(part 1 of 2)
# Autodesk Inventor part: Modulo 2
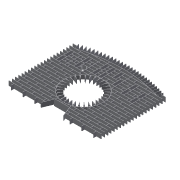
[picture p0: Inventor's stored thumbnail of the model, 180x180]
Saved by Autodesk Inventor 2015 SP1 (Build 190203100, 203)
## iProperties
Created: 2015-04
Part Number: Modulo 2
Material: Generic
Document SubType Name: Modeling
Designer: treina2
Density: 1 g/cm^3
Appearance: Default
Author: treina2
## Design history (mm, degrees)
sketch "Sketch1"
  geometry: L1 (740, 1360)-(740, 1418) reference; L2 (954, 1088)-(954, 1146) reference; L3 (740, 1088)-(740, 1146) reference; L4 (740, 1292)-(740, 1350) reference; L5 (954, 1224)-(954, 1282) reference; L6 (954, 1360)-(954, 1418) reference; L7 (954, 1292)-(954, 1350) reference; L8 (954, 1156)-(954, 1214) reference; L9 (740, 1156)-(740, 1214) reference; L10 (740, 1224)-(740, 1282) reference; L11 (1990, 534)-(1990, 544) reference; L12 (1990, 1350)-(1990, 1360) reference; L13 (740, 262)-(500, 262) reference; L14 (500, 262)-(500, 204) reference; L15 (1875, 136)-(1990, 136) reference; L16 (1990, 136)-(1990, 194) reference; L17 (1990, 194)-(1875, 194) reference; L18 (1875, 194)-(1875, 136) reference; L19 (250, 68)-(490, 68) reference; L20 (490, 68)-(490, 126) reference; L21 (490, 126)-(250, 126) reference; L22 (250, 126)-(250, 68) reference; L23 (750, 68)-(777.045, 68) reference; L24 (1250, 204)-(1490, 204) reference; L25 (1490, 204)-(1490, 262) reference; L26 (1490, 262)-(1250, 262) reference; L27 (1250, 262)-(1250, 204) reference; L28 (1500, 204)-(1740, 204) reference; L29 (1740, 204)-(1740, 262) reference; L30 (1740, 262)-(1500, 262) reference; L31 (1500, 262)-(1500, 204) reference; L32 (125, 136)-(365, 136) reference; L33 (365, 136)-(365, 194) reference; L34 (365, 194)-(125, 194) reference; L35 (125, 194)-(125, 136) reference; L36 (0, 476)-(240, 476) reference; L37 (240, 476)-(240, 534) reference; L38 (240, 534)-(0, 534) reference; L39 (0, 534)-(0, 476) reference; L40 (115, 408)-(0, 408) reference; L41 (0, 408)-(0, 466) reference; L42 (0, 466)-(115, 466) reference; L43 (115, 466)-(115, 408) reference; L44 (1750, 1020)-(1990, 1020) reference; L45 (1990, 1020)-(1990, 1078) reference; L46 (1990, 1078)-(1750, 1078) reference; L47 (1750, 1078)-(1750, 1020) reference; L48 (375, 680)-(570.34, 680) reference; L49 (1500, 884)-(1740, 884) reference; L50 (1740, 884)-(1740, 942) reference; L51 (1740, 942)-(1500, 942) reference; L52 (1500, 942)-(1500, 884) reference; L53 (1750, 884)-(1990, 884) reference; L54 (1990, 884)-(1990, 942) reference; L55 (1990, 942)-(1750, 942) reference; L56 (1750, 942)-(1750, 884) reference; L57 (1250, 1292)-(1422, 1292) reference; L58 (750, 1020)-(764.401, 1020) reference; L59 (250, 1214)-(250, 1156) reference; L60 (250, 1156)-(308, 1156) reference; L61 (750, 1258)-(750, 1418) reference; L62 (750, 1418)-(808, 1418) reference; L63 (808, 1418)-(808, 1258) reference; L64 (808, 1258)-(750, 1258) reference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; C1 r 300 at (995, 663) reference; C2 r 300 at (995, 663) reference; C3 r 300 at (995, 663) reference; C4 r 300 at (995, 663) reference; C5 r 300 at (995, 663) reference; C6 r 300 at (995, 663) reference; A1 r 425 centre (995, 663) between (749.611, 1010) and (683.385, 952) reference; A2 r 2840.721 centre (995, -1354.721) between (490, 1440.752) and (423.896, 1428) reference; A3 r 425 centre (995, 663) between (1411.413, 748) and (1395.22, 806) reference; A4 r 425 centre (995, 663) between (1419.66, 680) and (1413.33, 738) reference; A5 r 425 centre (995, 663) between (863.689, 258.794) and (990, 238.029) reference; A6 r 425 centre (995, 663) between (594.78, 806) and (578.587, 748) reference; A7 r 2840.721 centre (995, -1354.721) between (1615, 1417.516) and (1612.83, 1418) reference; A8 r 425 centre (995, 663) between (903.348, 1078) and (764.401, 1020) reference; A9 r 425 centre (995, 663) between (1376.649, 476) and (1399.949, 534) reference; A10 r 425 centre (995, 663) between (662.735, 398) and (718.783, 340) reference; A11 r 425 centre (995, 663) between (1358.021, 884) and (1315.599, 942) reference; A12 r 425 centre (995, 663) between (1365, 872.105) and (1363.923, 874) reference; A13 r 425 centre (995, 663) between (1225.599, 1020) and (1086.652, 1078) reference; A14 r 425 centre (995, 663) between (1403, 544) and (1415.6, 602) reference; A15 r 425 centre (995, 663) between (1416.929, 612) and (1419.942, 670) reference; A16 r 425 centre (995, 663) between (1161.565, 272) and (1259.076, 330) reference; A17 r 425 centre (995, 663) between (1271.217, 340) and (1327.265, 398) reference; A18 r 425 centre (995, 663) between (1335, 408) and (1365, 453.895) reference; A19 r 425 centre (995, 663) between (574.4, 602) and (587, 544) reference; A20 r 425 centre (995, 663) between (590.051, 534) and (613.351, 476) reference; A21 r 425 centre (995, 663) between (1000, 238.029) and (1126.311, 258.794) reference; A22 r 425 centre (995, 663) between (576.67, 738) and (570.34, 680) reference; A23 r 425 centre (995, 663) between (730.924, 330) and (828.435, 272) reference; A24 r 425 centre (995, 663) between (615, 853.329) and (598.495, 816) reference; A25 r 425 centre (995, 663) between (626.077, 874) and (625, 872.105) reference; A26 r 2840.721 centre (995, -1354.721) between (1831.651, 1360) and (1625, 1415.26) reference; A27 r 425 centre (995, 663) between (674.401, 942) and (631.979, 884) reference; A28 r 2840.721 centre (995, -1354.721) between (365, 1415.26) and (158.349, 1360) reference; A29 r 2840.721 centre (995, -1354.721) between (990, 1485.996) and (750, 1475.415) reference; A30 r 2840.721 centre (995, -1354.721) between (740, 1474.532) and (500, 1442.54) reference; A31 r 2840.721 centre (995, -1354.721) between (377.17, 1418) and (375, 1417.516) reference; A32 r 425 centre (995, 663) between (570.058, 670) and (573.071, 612) reference; A33 r 425 centre (995, 663) between (1391.505, 816) and (1375, 853.329) reference; A34 r 425 centre (995, 663) between (625, 453.895) and (655, 408) reference; A35 r 425 centre (995, 663) between (1306.615, 952) and (1240.389, 1010) reference; A36 r 2840.721 centre (995, -1354.721) between (1490, 1442.54) and (1250, 1474.532) reference; A37 r 2840.721 centre (995, -1354.721) between (1240, 1475.415) and (1000, 1485.996) reference; A38 r 2840.721 centre (995, -1354.721) between (1566.104, 1428) and (1500, 1440.752) reference; 1 further point
  constraints: 2472 end point, 508 horizontal, 481 vertical, 127 point on line, 76 point on circle, 44 centre point, 1 midpoint, 1471 other
extrude "Extrusion1" new body sketch "Sketch1" distance "d0" = 115 (= T_P_L); taper "d1" = 0 deg
extrude "Extrusion2" new body sketch "Sketch1" distance "d2" = 115 (= T_P_L); taper "d3" = 0 deg
extrude "Extrusion3" new body sketch "Sketch1" distance "d4" = 115 (= T_P_L); taper "d5" = 0 deg
extrude "Extrusion4" new body sketch "Sketch1" distance "d6" = 115 (= T_P_L); taper "d7" = 0 deg
extrude "Extrusion6" new body sketch "Sketch1" distance "d10" = 115 (= T_P_L); taper "d11" = 0 deg
extrude "Extrusion7" new body sketch "Sketch1" distance "d12" = 115 (= T_P_L); taper "d13" = 0 deg
extrude "Extrusion8" new body sketch "Sketch1" distance "d14" = 115 (= T_P_L); taper "d15" = 0 deg
extrude "Extrusion9" new body sketch "Sketch1" distance "d16" = 115 (= T_P_L); taper "d17" = 0 deg
extrude "Extrusion10" new body sketch "Sketch1" distance "d18" = 115 (= T_P_L); taper "d19" = 0 deg
extrude "Extrusion11" new body sketch "Sketch1" distance "d20" = 115 (= T_P_L); taper "d21" = 0 deg
extrude "Extrusion12" new body sketch "Sketch1" distance "d22" = 115 (= T_P_L); taper "d23" = 0 deg
extrude "Extrusion13" new body sketch "Sketch1" distance "d24" = 115 (= T_P_L); taper "d25" = 0 deg
extrude "Extrusion14" new body sketch "Sketch1" distance "d26" = 115 (= T_P_L); taper "d27" = 0 deg
extrude "Extrusion15" new body sketch "Sketch1" distance "d28" = 115 (= T_P_L); taper "d29" = 0 deg
pattern_linear "Rectangular Pattern1" dims "d32" = 136 (= 2 x T_P_P + 2 x GAP)
pattern_linear "Rectangular Pattern2" dims "d35" = 136 (= 2 x T_P_P + 2 x GAP)
pattern_linear "Rectangular Pattern3" dims "d38" = 136 (= 2 x T_P_P + 2 x GAP)
pattern_linear "Rectangular Pattern4" dims "d41" = 136 (= 2 x T_P_P + 2 x GAP)
pattern_linear "Rectangular Pattern5" dims "d44" = 136 (= 2 x T_P_P + 2 x GAP)
pattern_linear "Rectangular Pattern6" dims "d47" = 136 (= 2 x T_P_P + 2 x GAP)
extrude "Extrusion16" new body sketch "Sketch1" distance "d48" = 115 (= T_P_L); taper "d49" = 0 deg
extrude "Extrusion17" new body sketch "Sketch1" distance "d50" = 115 (= T_P_L); taper "d51" = 0 deg
extrude "Extrusion18" new body sketch "Sketch1" distance "d52" = 115 (= T_P_L); taper "d53" = 0 deg
pattern_linear "Rectangular Pattern7" dims "d56" = 136 (= 2 x T_P_P + 2 x GAP)
pattern_linear "Rectangular Pattern8" dims "d59" = 136 (= 2 x T_P_P + 2 x GAP)
pattern_linear "Rectangular Pattern9" dims "d62" = 136 (= 2 x T_P_P + 2 x GAP)
pattern_linear "Rectangular Pattern10" dims "d65" = 136 (= 2 x T_P_P + 2 x GAP)
pattern_linear "Rectangular Pattern11" dims "d68" = 136 (= 2 x T_P_P + 2 x GAP)
extrude "Extrusion19" new body sketch "Sketch1" distance "d69" = 115 (= T_P_L); taper "d70" = 0 deg
extrude "Extrusion20" new body sketch "Sketch1" distance "d71" = 115 (= T_P_L); taper "d72" = 0 deg
extrude "Extrusion21" new body sketch "Sketch1" distance "d73" = 115 (= T_P_L); taper "d74" = 0 deg
extrude "Extrusion22" new body sketch "Sketch1" distance "d75" = 115 (= T_P_L); taper "d76" = 0 deg
extrude "Extrusion25" new body sketch "Sketch1" distance "d81" = 115 (= T_P_L); taper "d82" = 0 deg
extrude "Extrusion26" new body sketch "Sketch1" distance "d83" = 115 (= T_P_L); taper "d84" = 0 deg
extrude "Extrusion27" new body sketch "Sketch1" distance "d85" = 115 (= T_P_L); taper "d86" = 0 deg
extrude "Extrusion28" new body sketch "Sketch1" distance "d87" = 115 (= T_P_L); taper "d88" = 0 deg
extrude "Extrusion29" new body sketch "Sketch1" distance "d89" = 115 (= T_P_L); taper "d90" = 0 deg
extrude "Extrusion30" new body sketch "Sketch1" distance "d91" = 115 (= T_P_L); taper "d92" = 0 deg
extrude "Extrusion31" new body sketch "Sketch1" distance "d93" = 115 (= T_P_L); taper "d94" = 0 deg
extrude "Extrusion32" new body sketch "Sketch1" distance "d95" = 115 (= T_P_L); taper "d96" = 0 deg
extrude "Extrusion33" new body sketch "Sketch1" distance "d97" = 115 (= T_P_L); taper "d98" = 0 deg
extrude "Extrusion34" new body sketch "Sketch1" distance "d99" = 115 (= T_P_L); taper "d100" = 0 deg
extrude "Extrusion35" new body sketch "Sketch1" distance "d101" = 115 (= T_P_L); taper "d102" = 0 deg
extrude "Extrusion36" new body sketch "Sketch1" distance "d103" = 115 (= T_P_L); taper "d104" = 0 deg
extrude "Extrusion37" new body sketch "Sketch1" distance "d105" = 115 (= T_P_L); taper "d106" = 0 deg
extrude "Extrusion38" new body sketch "Sketch1" distance "d107" = 115 (= T_P_L); taper "d108" = 0 deg
extrude "Extrusion39" new body sketch "Sketch1" distance "d109" = 115 (= T_P_L); taper "d110" = 0 deg
extrude "Extrusion40" new body sketch "Sketch1" distance "d111" = 115 (= T_P_L); taper "d112" = 0 deg
extrude "Extrusion41" new body sketch "Sketch1" distance "d113" = 115 (= T_P_L); taper "d114" = 0 deg
extrude "Extrusion42" new body sketch "Sketch1" distance "d115" = 115 (= T_P_L); taper "d116" = 0 deg
extrude "Extrusion43" new body sketch "Sketch1" distance "d117" = 115 (= T_P_L); taper "d118" = 0 deg
extrude "Extrusion44" new body sketch "Sketch1" distance "d119" = 115 (= T_P_L); taper "d120" = 0 deg
extrude "Extrusion45" new body sketch "Sketch1" distance "d121" = 115 (= T_P_L); taper "d122" = 0 deg
extrude "Extrusion46" new body sketch "Sketch1" distance "d123" = 115 (= T_P_L); taper "d124" = 0 deg
extrude "Extrusion47" new body sketch "Sketch1" distance "d125" = 115 (= T_P_L); taper "d126" = 0 deg
extrude "Extrusion48" new body sketch "Sketch1" distance "d127" = 115 (= T_P_L); taper "d128" = 0 deg
extrude "Extrusion49" new body sketch "Sketch1" distance "d129" = 115 (= T_P_L); taper "d130" = 0 deg
extrude "Extrusion50" new body sketch "Sketch1" distance "d131" = 115 (= T_P_L); taper "d132" = 0 deg
extrude "Extrusion51" new body sketch "Sketch1" distance "d133" = 115 (= T_P_L); taper "d134" = 0 deg
extrude "Extrusion52" new body sketch "Sketch1" distance "d135" = 115 (= T_P_L); taper "d136" = 0 deg
extrude "Extrusion53" new body sketch "Sketch1" distance "d137" = 115 (= T_P_L); taper "d138" = 0 deg
pattern_linear "Rectangular Pattern12" dims "d141" = 136 (= 2 x T_P_P + 2 x GAP)
pattern_linear "Rectangular Pattern13" dims "d144" = 136 (= 2 x T_P_P + 2 x GAP)
extrude "Extrusion54" new body sketch "Sketch1" distance "d145" = 115 (= T_P_L); taper "d146" = 0 deg
extrude "Extrusion55" new body sketch "Sketch1" distance "d147" = 115 (= T_P_L); taper "d148" = 0 deg
extrude "Extrusion56" new body sketch "Sketch1" distance "d149" = 115 (= T_P_L); taper "d150" = 0 deg
extrude "Extrusion57" new body sketch "Sketch1" distance "d151" = 115 (= T_P_L); taper "d152" = 0 deg
extrude "Extrusion58" new body sketch "Sketch1" distance "d153" = 115 (= T_P_L); taper "d154" = 0 deg
extrude "Extrusion59" new body sketch "Sketch1" distance "d155" = 115 (= T_P_L); taper "d156" = 0 deg
extrude "Extrusion60" new body sketch "Sketch1" distance "d157" = 115 (= T_P_L); taper "d158" = 0 deg
extrude "Extrusion61" new body sketch "Sketch1" distance "d159" = 115 (= T_P_L); taper "d160" = 0 deg
extrude "Extrusion62" new body sketch "Sketch1" distance "d161" = 115 (= T_P_L); taper "d162" = 0 deg
pattern_linear "Rectangular Pattern14" dims "d165" = 68 (= T_P_P + GAP)
extrude "Extrusion63" new body sketch "Sketch1" distance "d166" = 115 (= T_P_L); taper "d167" = 0 deg
extrude "Extrusion64" new body sketch "Sketch1" distance "d168" = 115 (= T_P_L); taper "d169" = 0 deg
extrude "Extrusion65" new body sketch "Sketch1" distance "d170" = 115 (= T_P_L); taper "d171" = 0 deg
extrude "Extrusion66" new body sketch "Sketch1" distance "d172" = 115 (= T_P_L); taper "d173" = 0 deg
extrude "Extrusion67" new body sketch "Sketch1" distance "d174" = 115 (= T_P_L); taper "d175" = 0 deg
extrude "Extrusion68" new body sketch "Sketch1" distance "d176" = 115 (= T_P_L); taper "d177" = 0 deg
extrude "Extrusion69" new body sketch "Sketch1" distance "d178" = 115 (= T_P_L); taper "d179" = 0 deg
extrude "Extrusion70" new body sketch "Sketch1" distance "d180" = 115 (= T_P_L); taper "d181" = 0 deg
pattern_linear "Rectangular Pattern15" dims "d184" = 68 (= T_P_P + GAP)
extrude "Extrusion71" new body sketch "Sketch1" distance "d185" = 115 (= T_P_L); taper "d186" = 0 deg
extrude "Extrusion72" new body sketch "Sketch1" distance "d187" = 115 (= T_P_L); taper "d188" = 0 deg
extrude "Extrusion73" new body sketch "Sketch1" distance "d189" = 115 (= T_P_L); taper "d190" = 0 deg
extrude "Extrusion74" new body sketch "Sketch1" distance "d191" = 115 (= T_P_L); taper "d192" = 0 deg
extrude "Extrusion75" new body sketch "Sketch1" distance "d193" = 115 (= T_P_L); taper "d194" = 0 deg
extrude "Extrusion76" new body sketch "Sketch1" distance "d195" = 115 (= T_P_L); taper "d196" = 0 deg
extrude "Extrusion77" new body sketch "Sketch1" distance "d197" = 115 (= T_P_L); taper "d198" = 0 deg
extrude "Extrusion78" new body sketch "Sketch1" distance "d199" = 115 (= T_P_L); taper "d200" = 0 deg
extrude "Extrusion79" new body sketch "Sketch1" distance "d201" = 115 (= T_P_L); taper "d202" = 0 deg
extrude "Extrusion80" new body sketch "Sketch1" distance "d203" = 115 (= T_P_L); taper "d204" = 0 deg
extrude "Extrusion81" new body sketch "Sketch1" distance "d205" = 115 (= T_P_L); taper "d206" = 0 deg
extrude "Extrusion82" new body sketch "Sketch1" distance "d207" = 115 (= T_P_L); taper "d208" = 0 deg
extrude "Extrusion83" new body sketch "Sketch1" distance "d209" = 115 (= T_P_L); taper "d210" = 0 deg
extrude "Extrusion84" new body sketch "Sketch1" distance "d211" = 115 (= T_P_L); taper "d212" = 0 deg
extrude "Extrusion85" new body sketch "Sketch1" distance "d213" = 115 (= T_P_L); taper "d214" = 0 deg
extrude "Extrusion86" new body sketch "Sketch1" distance "d215" = 115 (= T_P_L); taper "d216" = 0 deg
extrude "Extrusion87" new body sketch "Sketch1" distance "d217" = 115 (= T_P_L); taper "d218" = 0 deg
extrude "Extrusion88" new body sketch "Sketch1" distance "d219" = 115 (= T_P_L); taper "d220" = 0 deg
extrude "Extrusion89" new body sketch "Sketch1" distance "d221" = 115 (= T_P_L); taper "d222" = 0 deg
extrude "Extrusion90" new body sketch "Sketch1" distance "d223" = 115 (= T_P_L); taper "d224" = 0 deg
extrude "Extrusion91" new body sketch "Sketch1" distance "d225" = 115 (= T_P_L); taper "d226" = 0 deg
extrude "Extrusion92" new body sketch "Sketch1" distance "d227" = 115 (= T_P_L); taper "d228" = 0 deg
extrude "Extrusion93" new body sketch "Sketch1" distance "d229" = 115 (= T_P_L); taper "d230" = 0 deg
extrude "Extrusion94" new body sketch "Sketch1" distance "d231" = 115 (= T_P_L); taper "d232" = 0 deg
extrude "Extrusion95" new body sketch "Sketch1" distance "d233" = 115 (= T_P_L); taper "d234" = 0 deg
extrude "Extrusion96" new body sketch "Sketch1" distance "d235" = 115 (= T_P_L); taper "d236" = 0 deg
extrude "Extrusion97" new body sketch "Sketch1" distance "d237" = 115 (= T_P_L); taper "d238" = 0 deg
extrude "Extrusion98" new body sketch "Sketch1" distance "d239" = 115 (= T_P_L); taper "d240" = 0 deg
extrude "Extrusion99" new body sketch "Sketch1" distance "d241" = 115 (= T_P_L); taper "d242" = 0 deg
extrude "Extrusion100" new body sketch "Sketch1" distance "d243" = 115 (= T_P_L); taper "d244" = 0 deg
extrude "Extrusion101" new body sketch "Sketch1" distance "d245" = 115 (= T_P_L); taper "d246" = 0 deg
extrude "Extrusion102" new body sketch "Sketch1" distance "d247" = 115 (= T_P_L); taper "d248" = 0 deg
extrude "Extrusion103" new body sketch "Sketch1" distance "d249" = 115 (= T_P_L); taper "d250" = 0 deg
extrude "Extrusion104" new body sketch "Sketch1" distance "d251" = 115 (= T_P_L); taper "d252" = 0 deg
extrude "Extrusion105" new body sketch "Sketch1" distance "d253" = 115 (= T_P_L); taper "d254" = 0 deg
workplane "Work Plane1"
sketch "Sketch2"
  geometry: L1 (0, 1292)-(0, 1350); L2 (214, 1020)-(214, 1078); L3 (0, 1020)-(0, 1078); L4 (0, 1224)-(0, 1282); L5 (214, 1156)-(214, 1214); L6 (214, 1292)-(214, 1350); L7 (214, 1224)-(214, 1282); L8 (214, 1088)-(214, 1146); L9 (0, 1088)-(0, 1146); L10 (0, 1156)-(0, 1214); L11 (1250, 466)-(1250, 476); L12 (1250, 1282)-(1250, 1292); L13 (0, 194)-(-240, 194); L14 (-240, 194)-(-240, 136); L15 (1135, 68)-(1250, 68); L16 (1250, 68)-(1250, 126); L17 (1250, 126)-(1135, 126); L18 (1135, 126)-(1135, 68); L19 (-490, 0)-(-250, 0); L20 (-250, 0)-(-250, 58); L21 (-250, 58)-(-490, 58); L22 (-490, 58)-(-490, 0); L23 (10, 0)-(37.045, 0); L24 (510, 136)-(750, 136); L25 (750, 136)-(750, 194); L26 (750, 194)-(510, 194); L27 (510, 194)-(510, 136); L28 (760, 136)-(1000, 136); L29 (1000, 136)-(1000, 194); L30 (1000, 194)-(760, 194); L31 (760, 194)-(760, 136); L32 (-615, 68)-(-375, 68); L33 (-375, 68)-(-375, 126); L34 (-375, 126)-(-615, 126); L35 (-615, 126)-(-615, 68); L36 (-740, 408)-(-500, 408); L37 (-500, 408)-(-500, 466); L38 (-500, 466)-(-740, 466); L39 (-740, 466)-(-740, 408); L40 (-625, 340)-(-740, 340); L41 (-740, 340)-(-740, 398); L42 (-740, 398)-(-625, 398); L43 (-625, 398)-(-625, 340); L44 (1010, 952)-(1250, 952); L45 (1250, 952)-(1250, 1010); L46 (1250, 1010)-(1010, 1010); L47 (1010, 1010)-(1010, 952); L48 (-365, 612)-(-169.66, 612); L49 (760, 816)-(1000, 816); L50 (1000, 816)-(1000, 874); L51 (1000, 874)-(760, 874); L52 (760, 874)-(760, 816); L53 (1010, 816)-(1250, 816); L54 (1250, 816)-(1250, 874); L55 (1250, 874)-(1010, 874); L56 (1010, 874)-(1010, 816); L57 (510, 1224)-(682, 1224); L58 (10, 952)-(24.401, 952); L59 (-490, 1146)-(-490, 1088); L60 (-490, 1088)-(-432, 1088); L61 (10, 1190)-(10, 1350); L62 (10, 1350)-(68, 1350); L63 (68, 1350)-(68, 1190); L64 (68, 1190)-(10, 1190)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; C1 r 300 at (255, 595); C2 r 300 at (255, 595); C3 r 300 at (255, 595); C4 r 300 at (255, 595); C5 r 300 at (255, 595); C6 r 300 at (255, 595); A1 r 425 centre (255, 595) between (9.611, 942) and (-56.615, 884); A2 r 2840.721 centre (255, -1422.721) between (-250, 1372.752) and (-316.104, 1360); A3 r 425 centre (255, 595) between (671.413, 680) and (655.22, 738); A4 r 425 centre (255, 595) between (679.66, 612) and (673.33, 670); A5 r 425 centre (255, 595) between (123.689, 190.794) and (250, 170.029); A6 r 425 centre (255, 595) between (-145.22, 738) and (-161.413, 680); A7 r 2840.721 centre (255, -1422.721) between (875, 1349.516) and (872.83, 1350); A8 r 425 centre (255, 595) between (163.348, 1010) and (24.401, 952); A9 r 425 centre (255, 595) between (636.649, 408) and (659.949, 466); A10 r 425 centre (255, 595) between (-77.265, 330) and (-21.217, 272); A11 r 425 centre (255, 595) between (618.021, 816) and (575.599, 874); A12 r 425 centre (255, 595) between (625, 804.105) and (623.923, 806); A13 r 425 centre (255, 595) between (485.599, 952) and (346.652, 1010); A14 r 425 centre (255, 595) between (663, 476) and (675.6, 534); A15 r 425 centre (255, 595) between (676.929, 544) and (679.942, 602); A16 r 425 centre (255, 595) between (421.565, 204) and (519.076, 262); A17 r 425 centre (255, 595) between (531.217, 272) and (587.265, 330); A18 r 425 centre (255, 595) between (595, 340) and (625, 385.895); A19 r 425 centre (255, 595) between (-165.6, 534) and (-153, 476); A20 r 425 centre (255, 595) between (-149.949, 466) and (-126.649, 408); A21 r 425 centre (255, 595) between (260, 170.029) and (386.311, 190.794); A22 r 425 centre (255, 595) between (-163.33, 670) and (-169.66, 612); A23 r 425 centre (255, 595) between (-9.076, 262) and (88.435, 204); A24 r 425 centre (255, 595) between (-125, 785.329) and (-141.505, 748); A25 r 425 centre (255, 595) between (-113.923, 806) and (-115, 804.105); A26 r 2840.721 centre (255, -1422.721) between (1091.651, 1292) and (885, 1347.26); A27 r 425 centre (255, 595) between (-65.599, 874) and (-108.021, 816); A28 r 2840.721 centre (255, -1422.721) between (-375, 1347.26) and (-581.651, 1292); A29 r 2840.721 centre (255, -1422.721) between (250, 1417.996) and (10, 1407.415); A30 r 2840.721 centre (255, -1422.721) between (0, 1406.532) and (-240, 1374.54); A31 r 2840.721 centre (255, -1422.721) between (-362.83, 1350) and (-365, 1349.516); A32 r 425 centre (255, 595) between (-169.942, 602) and (-166.929, 544); A33 r 425 centre (255, 595) between (651.505, 748) and (635, 785.329); A34 r 425 centre (255, 595) between (-115, 385.895) and (-85, 340); A35 r 425 centre (255, 595) between (566.615, 884) and (500.389, 942); A36 r 2840.721 centre (255, -1422.721) between (750, 1374.54) and (510, 1406.532); A37 r 2840.721 centre (255, -1422.721) between (500, 1407.415) and (260, 1417.996); A38 r 2840.721 centre (255, -1422.721) between (826.104, 1360) and (760, 1372.752); 2 further points
  constraints: 2472 end point, 127 point on line, 76 point on circle, 44 centre point, 1 midpoint
extrude "Extrusion106" new body sketch "Sketch2" distance "d255" = 15; taper "d257" = 0 deg; dims "d256" = 140 (derived), "d258" = 0
extrude "Extrusion107" new body sketch "Sketch2" distance "d259" = 15; taper "d261" = 0 deg; dims "d260" = 140 (derived), "d262" = 0
extrude "Extrusion108" new body sketch "Sketch2" distance "d263" = 15; taper "d265" = 0 deg; dims "d264" = 140 (derived), "d266" = 0
workplane "Work Plane2"
sketch "Sketch3"
  geometry: L1 (906.204, 951.021)-(963.017, 962.697) reference; L2 (963.017, 962.697)-(939.867, 1075.343) reference; L3 (939.867, 1075.343)-(883.055, 1063.667) reference; L4 (883.055, 1063.667)-(906.204, 951.021) reference; L5 (939.867, 1075.343)-(883.055, 1063.667); L6 (906.204, 951.021)-(883.055, 1063.667); L7 (963.017, 962.697)-(906.204, 951.021); L8 (939.867, 1075.343)-(963.017, 962.697); L9 (903.343, 950.124)-(850.043, 927.251); L10 (850.043, 927.251)-(804.693, 1032.931); L11 (857.992, 1055.804)-(903.343, 950.124); L12 (857.992, 1055.804)-(804.693, 1032.931); L13 (847.422, 925.796)-(799.817, 892.662); L14 (799.817, 892.662)-(734.122, 987.05); L15 (781.726, 1020.184)-(847.422, 925.796); L16 (781.726, 1020.184)-(734.122, 987.05); L17 (797.542, 890.709)-(757.582, 848.671); L18 (757.582, 848.671)-(674.231, 927.902); L19 (714.191, 969.94)-(797.542, 890.709); L20 (714.191, 969.94)-(674.231, 927.902); L21 (755.747, 846.3)-(725.067, 797.079); L22 (725.067, 797.079)-(627.473, 857.909); L23 (658.153, 907.131)-(755.747, 846.3); L24 (658.153, 907.131)-(627.473, 857.909); L25 (723.746, 794.386)-(703.603, 739.997); L26 (703.603, 739.997)-(595.761, 779.937); L27 (615.905, 834.326)-(723.746, 794.386); L28 (615.905, 834.326)-(595.761, 779.937); L29 (702.851, 737.094)-(694.068, 679.763); L30 (694.068, 679.763)-(580.394, 697.177); L31 (589.177, 754.508)-(702.851, 737.094); L32 (589.177, 754.508)-(580.394, 697.177); L33 (693.916, 676.768)-(696.854, 618.842); L34 (696.854, 618.842)-(582.001, 613.018); L35 (579.064, 670.943)-(693.916, 676.768); L36 (579.064, 670.943)-(582.001, 613.018); L37 (697.308, 615.878)-(711.846, 559.73); L38 (711.846, 559.73)-(600.517, 530.905); L39 (585.979, 587.053)-(697.308, 615.878); L40 (585.979, 587.053)-(600.517, 530.905); L41 (712.887, 556.918)-(738.43, 504.845); L42 (738.43, 504.845)-(635.183, 454.2); L43 (609.64, 506.273)-(712.887, 556.918); L44 (609.64, 506.273)-(635.183, 454.2); L45 (740.016, 502.301)-(775.518, 456.436); L46 (775.518, 456.436)-(684.579, 386.044); L47 (649.077, 431.909)-(740.016, 502.301); L48 (649.077, 431.909)-(684.579, 386.044); L49 (777.584, 454.262)-(821.592, 416.483); L50 (821.592, 416.483)-(746.684, 329.226); L51 (702.676, 367.005)-(777.584, 454.262); L52 (702.676, 367.005)-(746.684, 329.226); L53 (824.053, 414.77)-(874.765, 386.622); L54 (874.765, 386.622)-(818.956, 286.072); L55 (768.244, 314.22)-(824.053, 414.77); L56 (768.244, 314.22)-(818.956, 286.072); L57 (877.521, 385.44)-(932.861, 368.077); L58 (932.861, 368.077)-(898.434, 258.351); L59 (843.094, 275.714)-(877.521, 385.44); L60 (843.094, 275.714)-(898.434, 258.351); L61 (935.798, 367.473)-(993.501, 361.605); L62 (993.501, 361.605)-(981.866, 247.195); L63 (924.164, 253.063)-(935.798, 367.473); L64 (924.164, 253.063)-(981.866, 247.195)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; C1 r 156.317 at (995, 663); A1 r 425 centre (995, 663) between (1000, 238.029) and (1126.311, 258.794) reference; A2 r 425 centre (995, 663) between (863.689, 258.794) and (990, 238.029) reference; 2 further points
  constraints: 248 end point, 3 collinear, 1 centre point, 1 coincident, 249 other
  dimensions: "d270" = 360 deg dimension on point (995, 663) L1.end (derived)
  node "Project Cut Edges1"
extrude "Extrusion109" new body sketch "Sketch3" distance "d272" = 115 (derived); taper "d273" = 0 deg
workplane "Work Plane3"
sketch "Sketch4"
  geometry: L1 (308, 1146)-(193, 1146) reference; L2 (308, 1088)-(308, 1146) reference; L3 (193, 1088)-(308, 1088) reference; L4 (193, 1146)-(193, 1112) reference; L5 (193, 1122)-(193, 1088) reference; L6 (183, 1282)-(183, 1122) reference; L7 (183, 1282)-(125, 1282) reference; L8 (125, 1122)-(125, 1282) reference; L9 (183, 1122)-(125, 1122) reference; L10 (125, 1112)-(183, 1112) reference; L11 (125, 952)-(125, 1112) reference; L12 (183, 1112)-(183, 952) reference; L13 (183, 952)-(125, 952) reference; L14 (308, 1020)-(250, 1020) reference; L15 (250, 1078)-(250, 1020) reference; L16 (308, 1078)-(250, 1078) reference; L17 (308, 1078)-(308, 1020) reference; L18 (308, 952)-(308, 1010) reference; L19 (308, 1010)-(193, 1010) reference; L20 (193, 952)-(308, 952) reference; L21 (193, 1010)-(193, 952) reference; L22 (250, 1156)-(308, 1156) reference; L23 (308, 1214)-(308, 1156) reference; L24 (250, 1214)-(308, 1214) reference; L25 (250, 1214)-(250, 1156) reference; L26 (240, 1224)-(308, 1224) reference; L27 (308, 1224)-(308, 1282) reference; L28 (308, 1282)-(193, 1282) reference; L29 (193, 1282)-(193, 1224) reference; L30 (193, 1224)-(308, 1224) reference; L31 (490, 1292)-(490, 1350) reference; L32 (432, 1350)-(490, 1350) reference; L33 (432, 1282)-(432, 1350) reference; L34 (432, 1190)-(432, 1350) reference; L35 (490, 1350)-(490, 1190) reference; L36 (490, 1190)-(432, 1190) reference; L37 (432, 1180)-(490, 1180) reference; L38 (490, 1180)-(490, 1020) reference; L39 (432, 1020)-(432, 1180) reference; L40 (490, 1020)-(432, 1020) reference; L41 (500, 1135)-(547, 1088) reference; L42 (500, 1146)-(500, 1135) reference; L43 (571.024, 1146)-(500, 1146) reference; L44 (615, 1102.024)-(571.024, 1146) reference; L45 (615, 1020)-(615, 1088) reference; L46 (547, 1088)-(615, 1020) reference; L47 (615, 1088)-(615, 1102.024) reference; L48 (615, 1156)-(615, 1214) reference; L49 (615, 1214)-(500, 1214) reference; L50 (500, 1156)-(615, 1156) reference; L51 (500, 1190)-(500, 1156) reference; L52 (500, 1214)-(500, 1180) reference; L53 (567.5, 1224)-(615, 1224) reference; L54 (567.5, 1224)-(567.5, 1282) reference; L55 (615, 1282)-(615, 1224) reference; L56 (615, 1282)-(567.5, 1282) reference; L57 (500, 1292)-(615, 1292) reference; L58 (615, 1292)-(615, 1350) reference; L59 (500, 1350)-(500, 1292) reference; L60 (615, 1350)-(500, 1350) reference; L61 (750, 1418)-(808, 1418) reference; L62 (750, 1258)-(750, 1418) reference; L63 (808, 1258)-(750, 1258) reference; L64 (808, 1418)-(808, 1258) reference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; 1 further point
extrude "Extrusion110" new body sketch "Sketch4" distance "d278" = 115 (derived); taper "d279" = 0 deg
extrude "Extrusion111" new body sketch "Sketch4" distance "d280" = 115 (derived); taper "d281" = 0 deg
extrude "Extrusion112" new body sketch "Sketch4" distance "d282" = 115 (derived); taper "d283" = 0 deg
extrude "Extrusion113" new body sketch "Sketch4" distance "d284" = 115 (derived); taper "d285" = 0 deg
pattern_linear "Rectangular Pattern16" dims "d288" = 136 (derived)
pattern_linear "Rectangular Pattern17" dims "d291" = 136 (derived)
extrude "Extrusion114" new body sketch "Sketch4" distance "d292" = 115 (derived); taper "d293" = 0 deg
extrude "Extrusion115" new body sketch "Sketch4" distance "d294" = 115 (derived); taper "d295" = 0 deg
extrude "Extrusion116" new body sketch "Sketch4" distance "d296" = 115 (derived); taper "d297" = 0 deg
extrude "Extrusion117" new body sketch "Sketch4" distance "d298" = 115 (derived); taper "d299" = 0 deg
extrude "Extrusion118" new body sketch "Sketch4" distance "d300" = 115 (derived); taper "d301" = 0 deg
extrude "Extrusion119" new body sketch "Sketch4" distance "d302" = 115 (derived); taper "d303" = 0 deg
extrude "Extrusion120" new body sketch "Sketch4" distance "d304" = 115 (derived); taper "d305" = 0 deg
extrude "Extrusion121" new body sketch "Sketch4" distance "d306" = 115 (derived); taper "d307" = 0 deg
extrude "Extrusion122" new body sketch "Sketch4" distance "d308" = 115 (derived); taper "d309" = 0 deg
extrude "Extrusion123" new body sketch "Sketch4" distance "d310" = 115 (derived); taper "d311" = 0 deg
extrude "Extrusion124" new body sketch "Sketch4" distance "d312" = 115 (derived); taper "d313" = 0 deg
extrude "Extrusion125" new body sketch "Sketch4" distance "d314" = 115 (derived); taper "d315" = 0 deg
extrude "Extrusion126" new body sketch "Sketch4" distance "d316" = 115 (derived); taper "d317" = 0 deg
extrude "Extrusion127" new body sketch "Sketch4" distance "d318" = 115 (derived); taper "d319" = 0 deg
extrude "Extrusion128" new body sketch "Sketch4" distance "d320" = 115 (derived); taper "d321" = 0 deg
extrude "Extrusion129" new body sketch "Sketch4" distance "d322" = 115 (derived); taper "d323" = 0 deg
extrude "Extrusion130" new body sketch "Sketch4" distance "d324" = 115 (derived); taper "d325" = 0 deg
extrude "Extrusion131" new body sketch "Sketch4" distance "d326" = 115 (derived); taper "d327" = 0 deg
extrude "Extrusion132" new body sketch "Sketch4" distance "d328" = 115 (derived); taper "d329" = 0 deg
extrude "Extrusion133" new body sketch "Sketch4" distance "d330" = 115 (derived); taper "d331" = 0 deg
extrude "Extrusion134" new body sketch "Sketch4" distance "d332" = 115 (derived); taper "d333" = 0 deg
extrude "Extrusion135" new body sketch "Sketch4" distance "d334" = 115 (derived); taper "d335" = 0 deg
sketch "Sketch5"
  geometry: L1 (740, 1360)-(740, 1418); L2 (954, 1088)-(954, 1146); L3 (740, 1088)-(740, 1146); L4 (740, 1292)-(740, 1350); L5 (954, 1224)-(954, 1282); L6 (954, 1360)-(954, 1418); L7 (954, 1292)-(954, 1350); L8 (954, 1156)-(954, 1214); L9 (740, 1156)-(740, 1214); L10 (740, 1224)-(740, 1282); L11 (1990, 534)-(1990, 544); L12 (1990, 1350)-(1990, 1360); L13 (740, 262)-(500, 262); L14 (500, 262)-(500, 204); L15 (1875, 136)-(1990, 136); L16 (1990, 136)-(1990, 194); L17 (1990, 194)-(1875, 194); L18 (1875, 194)-(1875, 136); L19 (250, 68)-(490, 68); L20 (490, 68)-(490, 126); L21 (490, 126)-(250, 126); L22 (250, 126)-(250, 68); L23 (750, 68)-(777.045, 68); L24 (1250, 204)-(1490, 204); L25 (1490, 204)-(1490, 262); L26 (1490, 262)-(1250, 262); L27 (1250, 262)-(1250, 204); L28 (1500, 204)-(1740, 204); L29 (1740, 204)-(1740, 262); L30 (1740, 262)-(1500, 262); L31 (1500, 262)-(1500, 204); L32 (125, 136)-(365, 136); L33 (365, 136)-(365, 194); L34 (365, 194)-(125, 194); L35 (125, 194)-(125, 136); L36 (0, 476)-(240, 476); L37 (240, 476)-(240, 534); L38 (240, 534)-(0, 534); L39 (0, 534)-(0, 476); L40 (115, 408)-(0, 408); L41 (0, 408)-(0, 466); L42 (0, 466)-(115, 466); L43 (115, 466)-(115, 408); L44 (1750, 1020)-(1990, 1020); L45 (1990, 1020)-(1990, 1078); L46 (1990, 1078)-(1750, 1078); L47 (1750, 1078)-(1750, 1020); L48 (375, 680)-(570.34, 680); L49 (1500, 884)-(1740, 884); L50 (1740, 884)-(1740, 942); L51 (1740, 942)-(1500, 942); L52 (1500, 942)-(1500, 884); L53 (1750, 884)-(1990, 884); L54 (1990, 884)-(1990, 942); L55 (1990, 942)-(1750, 942); L56 (1750, 942)-(1750, 884); L57 (1250, 1292)-(1422, 1292); L58 (750, 1020)-(764.401, 1020); L59 (250, 1214)-(250, 1156); L60 (250, 1156)-(308, 1156); L61 (750, 1258)-(750, 1418); L62 (750, 1418)-(808, 1418); L63 (808, 1418)-(808, 1258); L64 (808, 1258)-(750, 1258)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; C1 r 300 at (995, 663); C2 r 300 at (995, 663); C3 r 300 at (995, 663); C4 r 300 at (995, 663); C5 r 300 at (995, 663); C6 r 300 at (995, 663); A1 r 425 centre (995, 663) between (749.611, 1010) and (683.385, 952); A2 r 2840.721 centre (995, -1354.721) between (490, 1440.752) and (423.896, 1428); A3 r 425 centre (995, 663) between (1411.413, 748) and (1395.22, 806); A4 r 425 centre (995, 663) between (1419.66, 680) and (1413.33, 738); A5 r 425 centre (995, 663) between (863.689, 258.794) and (990, 238.029); A6 r 425 centre (995, 663) between (594.78, 806) and (578.587, 748); A7 r 2840.721 centre (995, -1354.721) between (1615, 1417.516) and (1612.83, 1418); A8 r 425 centre (995, 663) between (903.348, 1078) and (764.401, 1020); A9 r 425 centre (995, 663) between (1376.649, 476) and (1399.949, 534); A10 r 425 centre (995, 663) between (662.735, 398) and (718.783, 340); A11 r 425 centre (995, 663) between (1358.021, 884) and (1315.599, 942); A12 r 425 centre (995, 663) between (1365, 872.105) and (1363.923, 874); A13 r 425 centre (995, 663) between (1225.599, 1020) and (1086.652, 1078); A14 r 425 centre (995, 663) between (1403, 544) and (1415.6, 602); A15 r 425 centre (995, 663) between (1416.929, 612) and (1419.942, 670); A16 r 425 centre (995, 663) between (1161.565, 272) and (1259.076, 330); A17 r 425 centre (995, 663) between (1271.217, 340) and (1327.265, 398); A18 r 425 centre (995, 663) between (1335, 408) and (1365, 453.895); A19 r 425 centre (995, 663) between (574.4, 602) and (587, 544); A20 r 425 centre (995, 663) between (590.051, 534) and (613.351, 476); A21 r 425 centre (995, 663) between (1000, 238.029) and (1126.311, 258.794); A22 r 425 centre (995, 663) between (576.67, 738) and (570.34, 680); A23 r 425 centre (995, 663) between (730.924, 330) and (828.435, 272); A24 r 425 centre (995, 663) between (615, 853.329) and (598.495, 816); A25 r 425 centre (995, 663) between (626.077, 874) and (625, 872.105); A26 r 2840.721 centre (995, -1354.721) between (1831.651, 1360) and (1625, 1415.26); A27 r 425 centre (995, 663) between (674.401, 942) and (631.979, 884); A28 r 2840.721 centre (995, -1354.721) between (365, 1415.26) and (158.349, 1360); A29 r 2840.721 centre (995, -1354.721) between (990, 1485.996) and (750, 1475.415); A30 r 2840.721 centre (995, -1354.721) between (740, 1474.532) and (500, 1442.54); A31 r 2840.721 centre (995, -1354.721) between (377.17, 1418) and (375, 1417.516); A32 r 425 centre (995, 663) between (570.058, 670) and (573.071, 612); A33 r 425 centre (995, 663) between (1391.505, 816) and (1375, 853.329); A34 r 425 centre (995, 663) between (625, 453.895) and (655, 408); A35 r 425 centre (995, 663) between (1306.615, 952) and (1240.389, 1010); A36 r 2840.721 centre (995, -1354.721) between (1490, 1442.54) and (1250, 1474.532); A37 r 2840.721 centre (995, -1354.721) between (1240, 1475.415) and (1000, 1485.996); A38 r 2840.721 centre (995, -1354.721) between (1566.104, 1428) and (1500, 1440.752); 3 further points
  constraints: 2472 end point, 127 point on line, 76 point on circle, 44 centre point, 1 midpoint
extrude "Extrusion136" new body sketch "Sketch5" distance "d336" = 115 (derived); taper "d337" = 0 deg
extrude "Extrusion137" new body sketch "Sketch5" distance "d338" = 115 (derived); taper "d339" = 0 deg
extrude "Extrusion138" new body sketch "Sketch5" distance "d340" = 115 (derived); taper "d341" = 0 deg
extrude "Extrusion139" new body sketch "Sketch5" distance "d342" = 115 (derived); taper "d343" = 0 deg
extrude "Extrusion140" new body sketch "Sketch5" distance "d344" = 115 (derived); taper "d345" = 0 deg
extrude "Extrusion141" new body sketch "Sketch5" distance "d346" = 115 (derived); taper "d347" = 0 deg
extrude "Extrusion142" new body sketch "Sketch5" distance "d348" = 115 (derived); taper "d349" = 0 deg
extrude "Extrusion143" new body sketch "Sketch5" distance "d350" = 115 (derived); taper "d351" = 0 deg
extrude "Extrusion144" new body sketch "Sketch5" distance "d352" = 115 (derived); taper "d353" = 0 deg
extrude "Extrusion145" new body sketch "Sketch5" distance "d354" = 115 (derived); taper "d355" = 0 deg
extrude "Extrusion146" new body sketch "Sketch5" distance "d356" = 115 (derived); taper "d357" = 0 deg
extrude "Extrusion147" new body sketch "Sketch5" distance "d358" = 115 (derived); taper "d359" = 0 deg
extrude "Extrusion148" new body sketch "Sketch5" distance "d360" = 115 (derived); taper "d361" = 0 deg
extrude "Extrusion149" new body sketch "Sketch5" distance "d362" = 115 (derived); taper "d363" = 0 deg
extrude "Extrusion150" new body sketch "Sketch5" distance "d364" = 115 (derived); taper "d365" = 0 deg
extrude "Extrusion151" new body sketch "Sketch5" distance "d366" = 115 (derived); taper "d367" = 0 deg
extrude "Extrusion152" new body sketch "Sketch5" distance "d368" = 115 (derived); taper "d369" = 0 deg
extrude "Extrusion153" new body sketch "Sketch5" distance "d370" = 115 (derived); taper "d371" = 0 deg
extrude "Extrusion154" new body sketch "Sketch5" distance "d372" = 115 (derived); taper "d373" = 0 deg
extrude "Extrusion155" new body sketch "Sketch5" distance "d374" = 115 (derived); taper "d375" = 0 deg
extrude "Extrusion156" new body sketch "Sketch5" distance "d376" = 115 (derived); taper "d377" = 0 deg
extrude "Extrusion157" new body sketch "Sketch5" distance "d378" = 115 (derived); taper "d379" = 0 deg
extrude "Extrusion158" new body sketch "Sketch5" distance "d380" = 115 (derived); taper "d381" = 0 deg
extrude "Extrusion159" new body sketch "Sketch5" distance "d382" = 115 (derived); taper "d383" = 0 deg
extrude "Extrusion160" new body sketch "Sketch5" distance "d384" = 115 (derived); taper "d385" = 0 deg
extrude "Extrusion161" new body sketch "Sketch5" distance "d386" = 115 (derived); taper "d387" = 0 deg
extrude "Extrusion162" new body sketch "Sketch5" distance "d388" = 115 (derived); taper "d389" = 0 deg
workplane "Work Plane4"
workplane "Work Plane5"
sketch "Sketch6"
  geometry: L1 (-412.081, 126)-(-489.238, -68) reference; L2 (-101.896, 136)-(-123.689, 190.794) reference; L3 (-20.762, -68)-(-97.919, 126) reference; L4 (-489.238, -68)-(-20.762, -68) reference; L5 (-386.311, 190.794)-(-408.104, 136) reference; L6 (-20.762, -68)-(-123.689, 190.794); L7 (-97.919, 126)-(-20.762, -68) reference; L8 (-20.762, -68)-(-489.238, -68); L9 (-489.238, -68)-(-386.311, 190.794); L10 (-395.798, 194)-(-418.865, 136) reference; A1 r 425 centre (-255, 595) between (-386.311, 190.794) and (-260, 170.029) reference; A2 r 425 centre (-255, 595) between (-250, 170.029) and (-123.689, 190.794) reference; A3 r 425 centre (-255, 595) between (-386.311, 190.794) and (-123.689, 190.794); 1 further point
  constraints: 6 end point, 2 collinear, 2 point on circle, 1 centre point, 1 parallel
extrude "Extrusion163" new body sketch "Sketch6" distance "d392" = 135; taper "d393" = 0 deg
workplane "Work Plane6"
sketch "Sketch7"
  geometry: L1 (-11.979, 117.796)-(-0.303, 60.983) reference; L2 (0, 58)-(0, 0) reference; L3 (0, 29)-(-300, 29); L4 (-6.141, 89.39)-(-300, 29); L5 (115, 0)-(115, 58) reference; C1 r 310 at (-300, 29); C2 r 405 at (-300, 29); 1 further point
  constraints: 4 end point, 2 centre point, 2 coincident, 2 midpoint, 1 horizontal, 1 perpendicular
  dimensions: "d395" = 10 distance edge to line of C1 L1; "d396" = 10 distance edge to line of C2 L5 (derived)
extrude "Extrusion164" join sketch "Sketch7" distance "d397" = 95; taper "d398" = 0 deg
workplane "Work Plane7"
sketch "Sketch8"
  geometry: L1 (-165.38, 874)-(-146.792, 816) reference; L2 (-10, 738)-(-250, 738) reference; L3 (1740, 874)-(1655.38, 874) reference; L4 (1633.588, 806)-(1625, 779.204) reference; L5 (1740, 738)-(1500, 738) reference; L6 (1740, 874)-(1740, -612); L7 (1740, -612)-(-250, -612); L8 (-250, -612)-(-250, 874); L9 (-250, 874)-(-165.38, 874); L10 (-165.38, 874)-(-124.847, 747.523); L11 (1740, 874)-(1655.38, 874); L12 (1655.38, 874)-(1614.847, 747.523); L13 (1655.38, 874)-(1636.792, 816) reference; C1 r 405 at (745, 51) reference; C2 r 436.685 at (745, 51); A1 r 2840.721 centre (745, -1966.721) between (115, 803.26) and (-91.651, 748) reference; A2 r 2840.721 centre (745, -1966.721) between (1581.651, 748) and (1375, 803.26) reference; A3 r 2767.321 centre (745, -1890.066) between (1611.795, 738) and (-121.795, 738); A4 r 2777.321 centre (745, -1890.066) between (1614.847, 747.523) and (-124.847, 747.523) reference; A5 r 2881.211 centre (745, -1890.066) between (1646.554, 846.46) and (-156.554, 846.46)
  constraints: 14 end point, 6 point on circle, 4 centre point, 4 point on line, 3 perpendicular, 2 collinear, 1 coincident, 1 horizontal, 1 vertical, 1 other
  dimensions: "d400" = 10 radial gap between concentric circles of A3 A4
extrude "Extrusion165" join sketch "Sketch8" distance "d401" = 95; taper "d402" = 0 deg
sketch "Sketch9"
  geometry: C1 r 405 at (-745, 51) reference; C2 r 435 at (-745, 51); A1 r 425 centre (-745, 51) between (-1169.942, 58) and (-1166.929, 0) reference; 1 further point
  constraints: 1 centre point, 1 coincident
  dimensions: "d405" = 10 radial gap between concentric circles of C2 A1
extrude "Extrusion166" cut sketch "Sketch9" stored distance "d403" = 215; taper "d404" = 0 deg
extrude "Extrusion167" join sketch "Sketch8" distance "d406" = 80; taper "d408" = 0 deg; dims "d407" = 15, "d409" = 0
sketch "Sketch10"
  geometry: L1 (-1490, 330)-(-1250, 330) reference; L2 (-1422, 330)-(-1422, 679.817); L3 (-1422, 679.817)-(-1500.197, 679.817); L4 (-1500.197, 679.817)-(-1500.197, 407.908); L5 (-1490, 670)-(-1490, 510) reference; L6 (-1500.197, 407.908)-(-1625, 407.908); L7 (-1625, 407.908)-(-1625, 330); L8 (-1625, 330)-(-1422, 330); L9 (-1365, 398)-(-1125, 398) reference; L10 (-1125, 748)-(-1365, 748) reference; L11 (-1172, 398)-(-1250, 398); L12 (-1250, 398)-(-1250, 748); L13 (-1250, 748)-(-1172, 748); L14 (-1172, 748)-(-1172, 398); L15 (-750, 816)-(-990, 816) reference; L16 (-1000, 466.079)-(-797, 466.079); L17 (-797, 466.079)-(-797, 816); L18 (-797, 816)-(-1000, 816); L19 (-1000, 816)-(-1000, 466.079); L20 (-490, 816)-(-704, 816); L21 (-704, 816)-(-704, 466.079); L22 (-704, 466.079)-(-490, 466.079); L23 (-490, 466.079)-(-490, 816); L24 (-125, 748)-(-365, 748) reference; L25 (-171.226, 748)-(-375, 748); L26 (-375, 748)-(-375, 398); L27 (-375, 398)-(-171.226, 398); L28 (-171.226, 398)-(-171.226, 748); L29 (-240, 330)-(0, 330) reference; L30 (135, 679.817)-(-68.82, 679.817); L31 (-68.82, 679.817)-(-68.82, 330); L32 (-68.82, 330)-(135, 330); L33 (135, 330)-(135, 679.817); 1 further point
  constraints: 52 end point, 11 parallel, 9 perpendicular, 8 point on line, 5 horizontal, 1 vertical
extrude "Extrusion168" cut sketch "Sketch10" distance "d410" = 1; taper "d411" = 0 deg
node "Direct Edit1"
combine "Combine2"
  node "M2.1"
  node "M2.2"
  node "M2.3"
  node "M2.4"
  node "M2.5"
  node "M2.7"
  node "M2.8"
  node "M2.9"
  node "M2.10"
  node "M2.11"
  node "M2.12"
  node "M2.13"
  node "M2.14"
  node "M2.15"
  node "M2.36"
  node "M2.37"
  node "M2.38"
  node "M2.39"
  node "M2.40"
  node "M2.78"
  node "M2.79"
  node "M2.80"
  node "M2.16"
  node "M2.17"
  node "M2.18"
  node "M2.19"
  node "M2.20"
  node "M2.21"
  node "M2.31"
  node "M2.32"
  node "M2.33"
  node "M2.34"
  node "M2.35"
  node "M2.25"
  node "M2.26"
  node "M2.27"
  node "M2.28"
  node "M2.29"
  node "M2.30"
  node "M2.22"
  node "M2.23"
  node "M2.24"
  node "M2.41"
  node "M2.42"
  node "M2.43"
  node "M2.44"
  body "Solid45"
  body "Solid46"
  body "Solid47"
  body "Solid48"
  body "Solid49"
  body "Solid50"
  body "Solid51"
  body "Solid52"
  body "Solid53"
  body "Solid54"
  body "Solid55"
  body "Solid56"
  body "Solid57"
  body "Solid58"
  body "Solid59"
  body "Solid60"
  body "Solid61"
  body "Solid62"
  body "Solid63"
  body "Solid64"
  body "Solid65"
  body "Solid66"
  body "Solid67"
  body "Solid68"
  body "Solid69"
  body "Solid70"
  body "Solid71"
  body "Solid72"
  body "Solid73"
  body "Solid74"
  body "Solid75"
  body "Solid76"
  body "Solid77"
  body "Solid81"
  body "Solid82"
  body "Solid83"
  body "Solid84"
  body "Solid87"
  body "Solid88"
  body "Solid89"
  body "Solid90"
  body "Solid91"
  body "Solid92"
  body "Solid93"
  body "Solid94"
  body "Solid95"
  body "Solid96"
  body "Solid97"
  body "Solid98"
  body "Solid99"
  body "Solid100"
  body "Solid101"
  body "Solid102"
  body "Solid103"
  body "Solid104"
  body "Solid105"
  body "Solid106"
  body "Solid107"
  body "Solid108"
  body "Solid109"
  body "Solid110"
  body "Solid111"
  body "Solid112"
  body "Solid113"
  body "Solid114"
  body "Solid115"
  body "Solid116"
  body "Solid117"
  body "Solid142"
  body "Solid143"
  body "Solid118"
  body "Solid119"
  body "Solid120"
  body "Solid121"
  body "Solid122"
  body "Solid123"
  body "Solid124"
  body "Solid125"
  body "Solid126"
  body "Solid140"
  body "Solid141"
  body "Solid127"
  body "Solid128"
  body "Solid129"
  body "Solid130"
  body "Solid131"
  body "Solid132"
  body "Solid133"
  body "Solid134"
  body "Solid135"
  body "Solid136"
  body "Solid137"
  body "Solid138"
  body "Solid139"
  body "Solid144"
  body "Solid145"
  body "Solid146"
  body "Solid147"
  body "Solid148"
  body "Solid149"
  body "Solid150"
  body "Solid151"
  body "Solid152"
  body "Solid153"
  body "Solid154"
  body "Solid155"
  body "Solid156"
  body "Solid157"
  body "Solid158"
  body "Solid159"
  body "Solid160"
  body "Solid161"
  body "Solid162"
  body "Solid163"
  body "Solid164"
  body "Solid165"
  body "Solid166"
  body "Solid167"
  body "Solid168"
  body "Solid169"
  body "Solid170"
  body "Solid171"
  body "Solid172"
  body "Solid173"
  body "Solid174"
  body "Solid175"
  body "Solid176"
  body "Solid177"
  body "Solid178"
  body "Solid180"
  body "Solid179"
  body "Solid181"
  body "Solid182"
  body "Solid183"
  body "Solid184"
  body "Solid185"
  body "Solid186"
  body "Solid187"
  body "Solid188"
  body "Solid189"
  body "Solid190"
  body "Solid191"
  body "Solid192"
  body "Solid193"
  body "Solid194"
  body "Solid195"
  body "Solid196"
  body "Solid197"
  body "Solid198"
  body "Solid199"
  body "Solid200"
  body "Solid201"
  body "Solid202"
  body "Solid203"
  body "Solid204"
  body "Solid205"
  body "Solid206"
  body "Solid207"
  body "Solid208"
  body "Solid209"
  body "Solid210"
  body "Solid211"
  body "Solid212"
  body "Solid213"
  body "Solid214"
  body "Solid215"
  body "Solid216"
  body "Solid217"
  body "Solid218"
  body "Solid219"
  body "Solid220"
  body "Solid221"
  body "Solid222"
  body "Solid223"
  body "Solid224"
  body "Solid225"
  body "Solid226"
  body "Solid227"
  body "Solid228"
  body "Solid229"
  body "Solid230"
  body "Solid231"
  body "Solid232"
  body "Solid233"
  body "Solid234"
  body "Solid235"
  body "Solid236"
  body "Solid237"
  body "Solid238"
  body "Solid239"
  body "Solid240"
  body "Solid241"
  body "Solid242"
  body "Solid243"
  body "Solid244"
  body "Solid245"
  body "Solid246"
  body "Solid247"
  body "Solid248"
  body "Solid249"
  body "Solid250"
  body "Solid251"
  body "Solid252"
  body "Solid253"
  body "Solid254"
  body "Solid255"
  body "Solid256"
  body "Solid257"
  body "Solid258"
  body "Solid259"
  body "Solid260"
  body "Solid261"
  body "Solid262"
  body "Solid263"
  body "Solid264"
  body "Solid265"
pattern_circular "Circular Pattern1" dims "d275" = 360 deg
feature "Pattern of M2.15:1"
feature "Pattern of M2.15:2"
feature "Pattern of M2.15:3"
feature "Pattern of M2.15:4"
feature "Pattern of M2.15:5"
feature "Pattern of M2.15:6"
feature "Pattern of M2.15:7"
feature "Pattern of M2.15:8"
feature "Pattern of M2.15:9"
feature "Pattern of M2.15:10"
feature "Pattern of M2.15:11"
feature "Pattern of M2.15:12"
feature "Pattern of M2.15:13"
feature "Pattern of M2.15:14"
feature "Pattern of M2.15:15"
feature "Pattern of M2.15:16"
feature "Pattern of M2.15:17"
feature "Pattern of M2.15:18"
feature "Pattern of M2.15:19"
feature "Pattern of M2.15:20"
feature "Pattern of M2.15:21"
feature "Pattern of M2.15:22"
feature "Pattern of M2.15:23"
